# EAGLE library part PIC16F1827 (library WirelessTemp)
PIC MICRO (16 I/O 10bit-5ch ADC 20MHz)
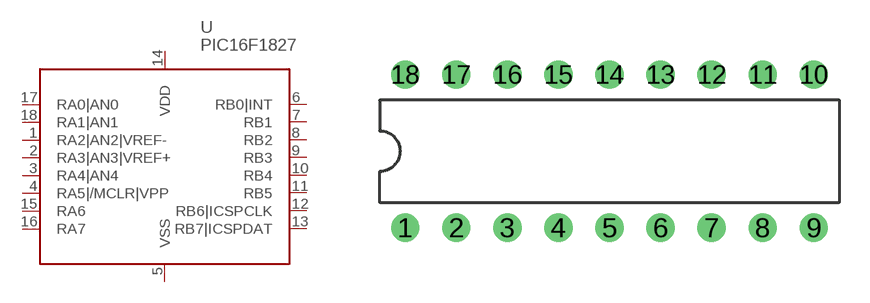
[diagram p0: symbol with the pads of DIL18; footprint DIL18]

Designator prefix U

## PIC16F1827DIL18  [DIL18]
1  RA2|AN2|VREF-
2  RA3|AN3|VREF+
3  RA4|AN4
4  RA5|/MCLR|VPP
5  VSS  pwr
6  RB0|INT
7  RB1
8  RB2
9  RB3
10  RB4
11  RB5
12  RB6|ICSPCLK
13  RB7|ICSPDAT
14  VDD  pwr
15  RA6
16  RA7
17  RA0|AN0
18  RA1|AN1

## Footprint DIL18 (pad centres in mm)
Dual In Line Package
drill 0.9 round: 1 -10.16,-3.81; 2 -7.62,-3.81; 3 -5.08,-3.81; 4 -2.54,-3.81; 5 0,-3.81; 6 2.54,-3.81; 7 5.08,-3.81; 8 7.62,-3.81; 9 10.16,-3.81; 10 10.16,3.81; 11 7.62,3.81; 12 5.08,3.81; 13 2.54,3.81; 14 0,3.81; 15 -2.54,3.81; 16 -5.08,3.81; 17 -7.62,3.81; 18 -10.16,3.81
